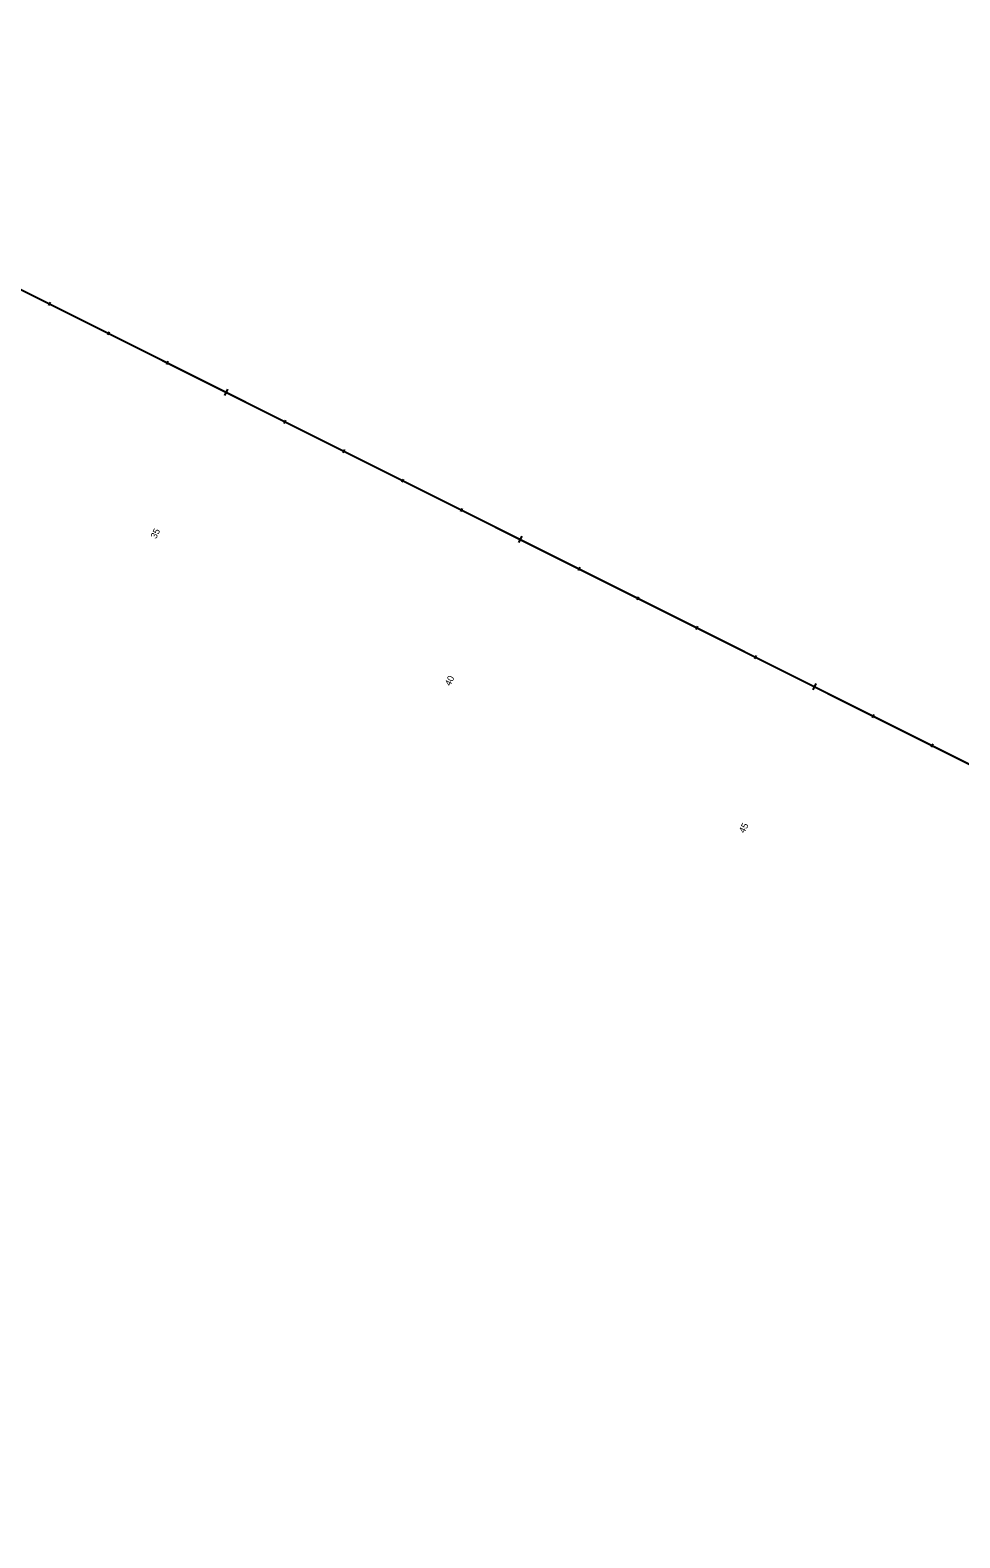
# Model space of a CAD drawing. Extents: x 2245492 to 2251120, y 200065 to 203543.
# Drawn here: x 2246893 to 2248307, y 201247 to 203539 of the extents above; entities that cross this region are included whole.
import ezdxf

# ---------------------------------------------------------------- set-up
doc = ezdxf.new("R2010")
doc.units = 0
for name, color, linetype in [('E_NCDOT_Terrain_Model_Contour_Minor', 7, 'Continuous'), ('E_NCDOT_Terrain_Model_Flow_Arrows', 7, 'Continuous'), ('E_NCDOT_Terrain_Model_Points_Low', 7, 'Continuous'), ('E_NCDOT_Terrain_Model_Spot_Elevation', 7, 'Continuous'), ('E_NCDOT_Terrain_Model_Triangle_Vertices', 7, 'Continuous')]:
    doc.layers.add(name, color=color, linetype=linetype)

msp = doc.modelspace()

# ---------------------------------------------------------------- linework, layer by layer
at = {"layer": 'E_NCDOT_Terrain_Model_Contour_Minor'}
msp.add_line((2246091.1, 203538.6), (2250670.6, 201246.8), dxfattribs=at)
at = {"layer": 'E_NCDOT_Terrain_Model_Flow_Arrows'}
for p, q in [((2247193.4, 202992.9), (2247188.7, 202983.4)), ((2247640.5, 202769.2), (2247635.8, 202759.7)), ((2248087.7, 202545.4), (2248082.9, 202535.9))]:
    msp.add_line(p, q, dxfattribs=at)
at = {"layer": 'E_NCDOT_Terrain_Model_Spot_Elevation'}
for p, q in [((2246924, 203124.9), (2246921.5, 203119.9)), ((2247013.4, 203080.1), (2247010.9, 203075.2)), ((2247102.8, 203035.4), (2247100.4, 203030.4)), ((2247192.3, 202990.6), (2247189.8, 202985.7)), ((2247281.7, 202945.9), (2247279.2, 202940.9)), ((2247371.1, 202901.1), (2247368.6, 202896.2)), ((2247460.5, 202856.3), (2247458.1, 202851.4)), ((2247550, 202811.6), (2247547.5, 202806.7)), ((2247728.8, 202722.1), (2247726.4, 202717.2)), ((2247818.2, 202677.3), (2247815.8, 202672.4)), ((2247907.7, 202632.6), (2247905.2, 202627.7)), ((2247997.1, 202587.8), (2247994.6, 202582.9)), ((2248086.5, 202543.1), (2248084.1, 202538.1)), ((2248176, 202498.3), (2248173.5, 202493.4)), ((2248265.4, 202453.6), (2248262.9, 202448.6))]:
    msp.add_line(p, q, dxfattribs=at)
at = {"layer": 'E_NCDOT_Terrain_Model_Triangle_Vertices'}
msp.add_line((2246230.2, 203468.9), (2250532.4, 201316), dxfattribs=at)

# ---------------------------------------------------------------- texts
at = {"layer": 'E_NCDOT_Terrain_Model_Points_Low'}
for s, p in [('35', (2247084.7, 202764.6)), ('40', (2247531.9, 202540.9)), ('45', (2247979, 202317.1))]:
    msp.add_text(s, height=10, rotation=63.4152, dxfattribs=at).set_placement(p)

doc.saveas('drawing.dxf')
